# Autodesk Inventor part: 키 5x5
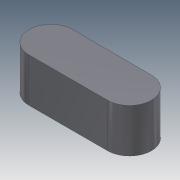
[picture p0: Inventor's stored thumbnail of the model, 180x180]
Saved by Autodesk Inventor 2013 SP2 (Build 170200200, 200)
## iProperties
Company: 한국ATC센터
Created: 2014-10
Part Number: 키 5x5
Document SubType Name: Modeling
Designer: KYOUNG IL JANG
Density: 1 g/cm^3
Mass: 0.323175 g
Surface Area: 2.9781 cm^2
Volume: 0.323175 cm^3
Material: 일반
Author: KYOUNG IL JANG
Revision Number: 1
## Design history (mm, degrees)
sketch "스케치1"
  geometry: L1 (-4.5, -2.5)-(4.5, -2.5); L2 (4.5, 2.5)-(-4.5, 2.5); A1 r 2.5 centre (4.5, 0) between (4.5, -2.5) and (4.5, 2.5); A2 r 2.5 centre (-4.5, 0) between (-4.5, 2.5) and (-4.5, -2.5); 2 further points
  constraints: 4 end point, 4 point on circle, 4 tangent, 2 centre point, 1 horizontal, 1 horizontal alignment, 1 midpoint, 1 parallel, 1 vertical alignment
  dimensions: "d0" = 5 distance between parallel lines of L1 L2; "d1" = 14 dimension on A1 A2
extrude "돌출1" new body sketch "스케치1" stored distance "d2" = 5; taper "d3" = 0 deg
node "솔리드1"
